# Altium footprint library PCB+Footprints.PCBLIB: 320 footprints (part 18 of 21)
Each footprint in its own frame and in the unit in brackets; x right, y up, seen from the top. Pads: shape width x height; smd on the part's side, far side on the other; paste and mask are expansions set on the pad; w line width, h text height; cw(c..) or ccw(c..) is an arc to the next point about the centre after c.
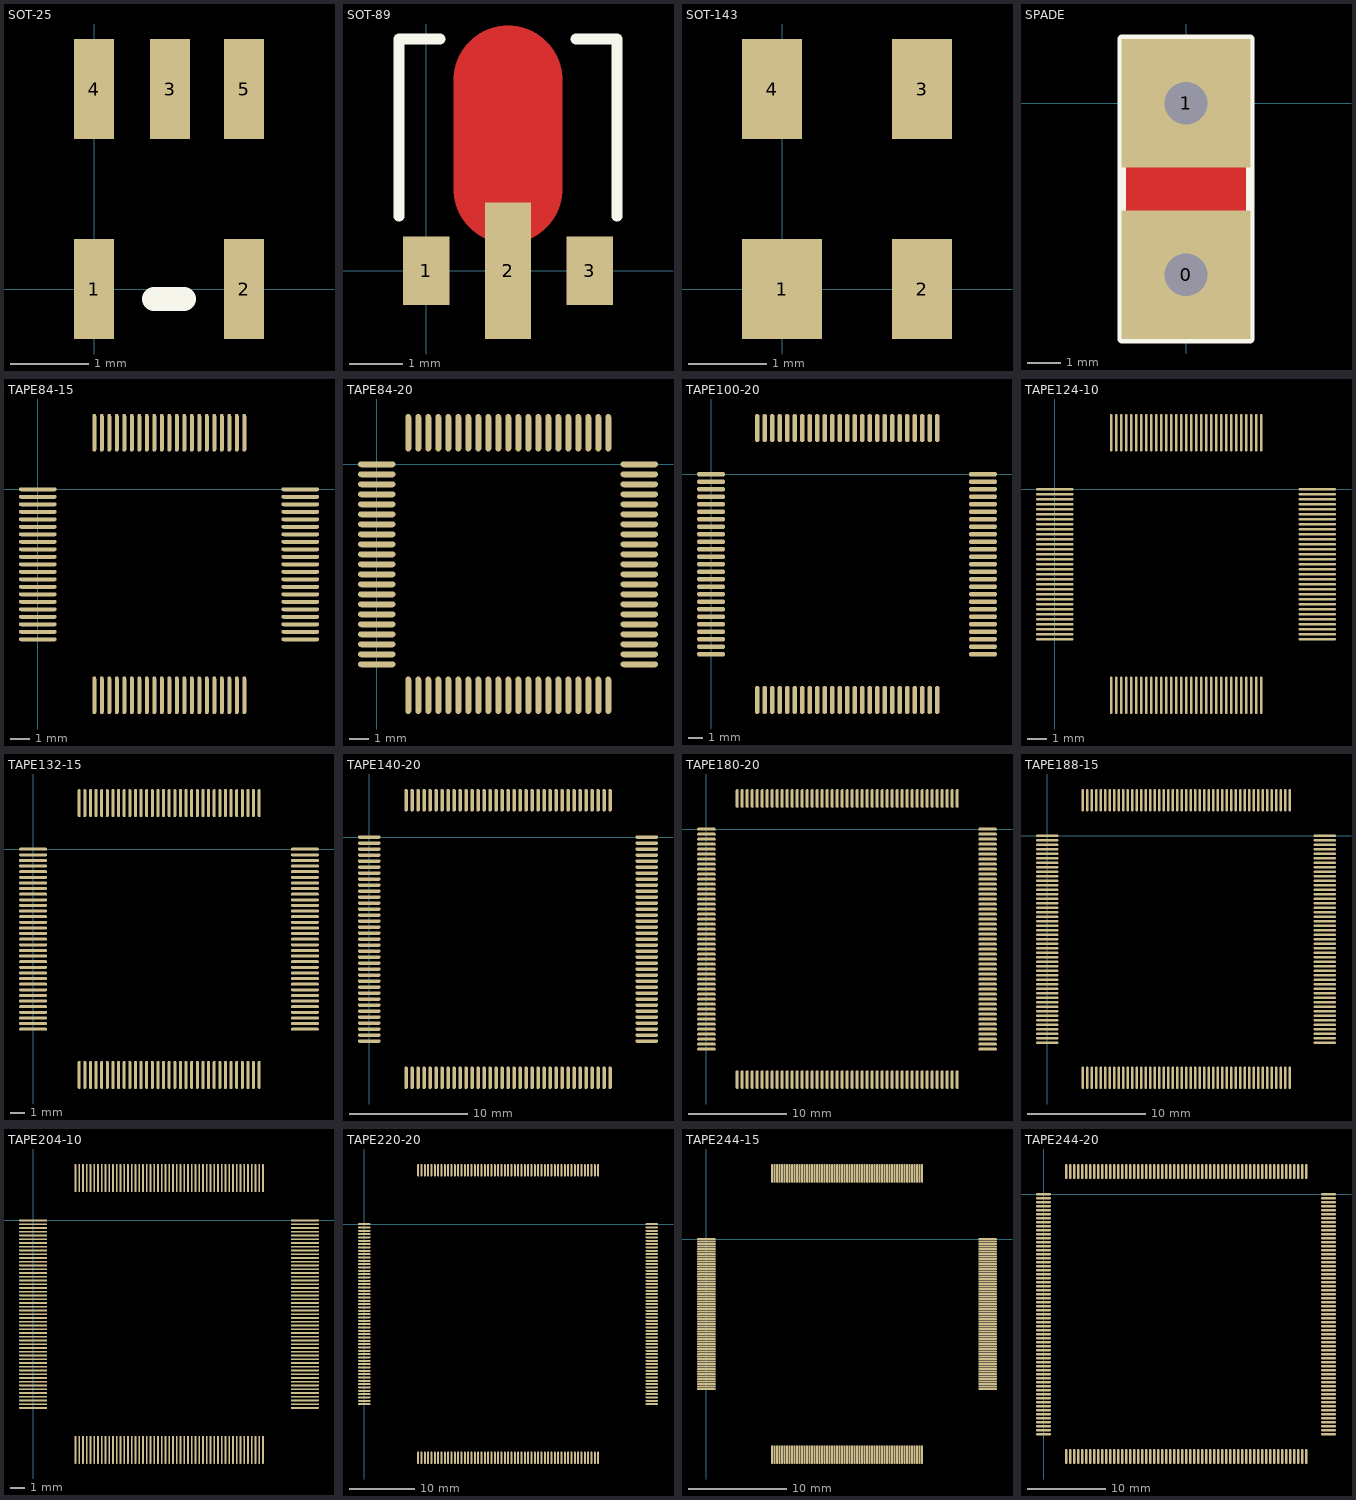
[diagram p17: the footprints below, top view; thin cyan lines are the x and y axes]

## SOT-25 [mil]
pads (5):
  rect 20x50 smd: 1(0,0) 2(75,0) 3(38,100) 4(0,100) 5(75,100)
TopOverlay:
  lines w12: 30,-5 45,-5

## SOT-89 [mil]
pads (3):
  rect 34x50 smd: 1(0,0) 3(120,0)
  rect 34x100 smd: 2(60,0)
TopLayer:
  lines w80: 60,60 60,140
TopOverlay:
  lines w8: -20,40 -20,170 10,170 ; 110,170 140,170 140,40

## SOT-143 [mil]
pads (4):
  rect 40x50 smd: 1(0,0)
  rect 30x50 smd: 2(70,0) 3(70,100) 4(-5,100)

## SPADE [mil]
pads (2):
  rect 150x150 hole 50: 0(0,-200) 1(0,0)
TopLayer:
  rectangle: -75,-150 75,-50
BottomLayer:
  rectangle: -75,-150 75,-50
TopOverlay:
  lines w10: -75,-275 75,-275 75,75 -75,75 -75,-275

## TAPE84-15 [mil]
pads (84):
  oval 75x8 smd: 1(0,0) 2(0,-15) 3(0,-30) 4(0,-45) 5(0,-60) 6(0,-75) 7(0,-90) 8(0,-105) 9(0,-120) 10(0,-135) 11(0,-150) 12(0,-165) 13(0,-180) 14(0,-195) 15(0,-210) 16(0,-225) 17(0,-240) 18(0,-255) 19(0,-270) 20(0,-285) 21(0,-300) 43(525,-300) 44(525,-285) 45(525,-270) 46(525,-255) 47(525,-240) 48(525,-225) 49(525,-210) 50(525,-195) 51(525,-180) 52(525,-165) 53(525,-150) 54(525,-135) 55(525,-120) 56(525,-105) 57(525,-90) 58(525,-75) 59(525,-60) 60(525,-45) 61(525,-30) 62(525,-15) 63(525,0)
  oval 8x75 smd: 22(113,-412) 23(128,-412) 24(143,-412) 25(158,-412) 26(173,-412) 27(188,-412) 28(203,-412) 29(218,-412) 30(233,-412) 31(248,-412) 32(263,-412) 33(278,-412) 34(293,-412) 35(308,-412) 36(323,-412) 37(338,-412) 38(353,-412) 39(368,-412) 40(383,-412) 41(398,-412) 42(413,-412) 64(413,113) 65(398,113) 66(383,113) 67(368,113) 68(353,113) 69(338,113) 70(323,113) 71(308,113) 72(293,113) 73(278,113) 74(263,113) 75(248,113) 76(233,113) 77(218,113) 78(203,113) 79(188,113) 80(173,113) 81(158,113) 82(143,113) 83(128,113) 84(113,113)

## TAPE84-20 [mil]
pads (84):
  oval 75x12 smd: 1(0,0) 2(0,-20) 3(0,-40) 4(0,-60) 5(0,-80) 6(0,-100) 7(0,-120) 8(0,-140) 9(0,-160) 10(0,-180) 11(0,-200) 12(0,-220) 13(0,-240) 14(0,-260) 15(0,-280) 16(0,-300) 17(0,-320) 18(0,-340) 19(0,-360) 20(0,-380) 21(0,-400) 43(525,-400) 44(525,-380) 45(525,-360) 46(525,-340) 47(525,-320) 48(525,-300) 49(525,-280) 50(525,-260) 51(525,-240) 52(525,-220) 53(525,-200) 54(525,-180) 55(525,-160) 56(525,-140) 57(525,-120) 58(525,-100) 59(525,-80) 60(525,-60) 61(525,-40) 62(525,-20) 63(525,0)
  oval 12x75 smd: 22(63,-462) 23(83,-462) 24(103,-462) 25(123,-462) 26(143,-462) 27(163,-462) 28(183,-462) 29(203,-462) 30(223,-462) 31(243,-462) 32(263,-462) 33(283,-462) 34(303,-462) 35(323,-462) 36(343,-462) 37(363,-462) 38(383,-462) 39(403,-462) 40(423,-462) 41(443,-462) 42(463,-462) 64(463,63) 65(443,63) 66(423,63) 67(403,63) 68(383,63) 69(363,63) 70(343,63) 71(323,63) 72(303,63) 73(283,63) 74(263,63) 75(243,63) 76(223,63) 77(203,63) 78(183,63) 79(163,63) 80(143,63) 81(123,63) 82(103,63) 83(83,63) 84(63,63)

## TAPE100-20 [mil]
pads (100):
  oval 75x12 smd: 1(0,0) 2(0,-20) 3(0,-40) 4(0,-60) 5(0,-80) 6(0,-100) 7(0,-120) 8(0,-140) 9(0,-160) 10(0,-180) 11(0,-200) 12(0,-220) 13(0,-240) 14(0,-260) 15(0,-280) 16(0,-300) 17(0,-320) 18(0,-340) 19(0,-360) 20(0,-380) 21(0,-400) 22(0,-420) 23(0,-440) 24(0,-460) 25(0,-480) 51(725,-480) 52(725,-460) 53(725,-440) 54(725,-420) 55(725,-400) 56(725,-380) 57(725,-360) 58(725,-340) 59(725,-320) 60(725,-300) 61(725,-280) 62(725,-260) 63(725,-240) 64(725,-220) 65(725,-200) 66(725,-180) 67(725,-160) 68(725,-140) 69(725,-120) 70(725,-100) 71(725,-80) 72(725,-60) 73(725,-40) 74(725,-20) 75(725,0)
  oval 12x75 smd: 26(123,-602) 27(143,-602) 28(163,-602) 29(183,-602) 30(203,-602) 31(223,-602) 32(243,-602) 33(263,-602) 34(283,-602) 35(303,-602) 36(323,-602) 37(343,-602) 38(363,-602) 39(383,-602) 40(403,-602) 41(423,-602) 42(443,-602) 43(463,-602) 44(483,-602) 45(503,-602) 46(523,-602) 47(543,-602) 48(563,-602) 49(583,-602) 50(603,-602) 76(603,123) 77(583,123) 78(563,123) 79(543,123) 80(523,123) 81(503,123) 82(483,123) 83(463,123) 84(443,123) 85(423,123) 86(403,123) 87(383,123) 88(363,123) 89(343,123) 90(323,123) 91(303,123) 92(283,123) 93(263,123) 94(243,123) 95(223,123) 96(203,123) 97(183,123) 98(163,123) 99(143,123) 100(123,123)

## TAPE124-10 [mil]
pads (124):
  oval 75x5 smd: 1(0,0) 2(0,-10) 3(0,-20) 4(0,-30) 5(0,-40) 6(0,-50) 7(0,-60) 8(0,-70) 9(0,-80) 10(0,-90) 11(0,-100) 12(0,-110) 13(0,-120) 14(0,-130) 15(0,-140) 16(0,-150) 17(0,-160) 18(0,-170) 19(0,-180) 20(0,-190) 21(0,-200) 22(0,-210) 23(0,-220) 24(0,-230) 25(0,-240) 26(0,-250) 27(0,-260) 28(0,-270) 29(0,-280) 30(0,-290) 31(0,-300) 63(525,-300) 64(525,-290) 65(525,-280) 66(525,-270) 67(525,-260) 68(525,-250) 69(525,-240) 70(525,-230) 71(525,-220) 72(525,-210) 73(525,-200) 74(525,-190) 75(525,-180) 76(525,-170) 77(525,-160) 78(525,-150) 79(525,-140) 80(525,-130) 81(525,-120) 82(525,-110) 83(525,-100) 84(525,-90) 85(525,-80) 86(525,-70) 87(525,-60) 88(525,-50) 89(525,-40) 90(525,-30) 91(525,-20) 92(525,-10) 93(525,0)
  oval 5x75 smd: 32(113,-412) 33(123,-412) 34(133,-412) 35(143,-412) 36(153,-412) 37(163,-412) 38(173,-412) 39(183,-412) 40(193,-412) 41(203,-412) 42(213,-412) 43(223,-412) 44(233,-412) 45(243,-412) 46(253,-412) 47(263,-412) 48(273,-412) 49(283,-412) 50(293,-412) 51(303,-412) 52(313,-412) 53(323,-412) 54(333,-412) 55(343,-412) 56(353,-412) 57(363,-412) 58(373,-412) 59(383,-412) 60(393,-412) 61(403,-412) 62(413,-412) 94(413,113) 95(403,113) 96(393,113) 97(383,113) 98(373,113) 99(363,113) 100(353,113) 101(343,113) 102(333,113) 103(323,113) 104(313,113) 105(303,113) 106(293,113) 107(283,113) 108(273,113) 109(263,113) 110(253,113) 111(243,113) 112(233,113) 113(223,113) 114(213,113) 115(203,113) 116(193,113) 117(183,113) 118(173,113) 119(163,113) 120(153,113) 121(143,113) 122(133,113) 123(123,113) 124(113,113)

## TAPE132-15 [mil]
pads (132):
  oval 75x8 smd: 1(0,0) 2(0,-15) 3(0,-30) 4(0,-45) 5(0,-60) 6(0,-75) 7(0,-90) 8(0,-105) 9(0,-120) 10(0,-135) 11(0,-150) 12(0,-165) 13(0,-180) 14(0,-195) 15(0,-210) 16(0,-225) 17(0,-240) 18(0,-255) 19(0,-270) 20(0,-285) 21(0,-300) 22(0,-315) 23(0,-330) 24(0,-345) 25(0,-360) 26(0,-375) 27(0,-390) 28(0,-405) 29(0,-420) 30(0,-435) 31(0,-450) 32(0,-465) 33(0,-480) 67(725,-480) 68(725,-465) 69(725,-450) 70(725,-435) 71(725,-420) 72(725,-405) 73(725,-390) 74(725,-375) 75(725,-360) 76(725,-345) 77(725,-330) 78(725,-315) 79(725,-300) 80(725,-285) 81(725,-270) 82(725,-255) 83(725,-240) 84(725,-225) 85(725,-210) 86(725,-195) 87(725,-180) 88(725,-165) 89(725,-150) 90(725,-135) 91(725,-120) 92(725,-105) 93(725,-90) 94(725,-75) 95(725,-60) 96(725,-45) 97(725,-30) 98(725,-15) 99(725,0)
  oval 8x75 smd: 34(123,-602) 35(138,-602) 36(153,-602) 37(168,-602) 38(183,-602) 39(198,-602) 40(213,-602) 41(228,-602) 42(243,-602) 43(258,-602) 44(273,-602) 45(288,-602) 46(303,-602) 47(318,-602) 48(333,-602) 49(348,-602) 50(363,-602) 51(378,-602) 52(393,-602) 53(408,-602) 54(423,-602) 55(438,-602) 56(453,-602) 57(468,-602) 58(483,-602) 59(498,-602) 60(513,-602) 61(528,-602) 62(543,-602) 63(558,-602) 64(573,-602) 65(588,-602) 66(603,-602) 100(603,123) 101(588,123) 102(573,123) 103(558,123) 104(543,123) 105(528,123) 106(513,123) 107(498,123) 108(483,123) 109(468,123) 110(453,123) 111(438,123) 112(423,123) 113(408,123) 114(393,123) 115(378,123) 116(363,123) 117(348,123) 118(333,123) 119(318,123) 120(303,123) 121(288,123) 122(273,123) 123(258,123) 124(243,123) 125(228,123) 126(213,123) 127(198,123) 128(183,123) 129(168,123) 130(153,123) 131(138,123) 132(123,123)

## TAPE140-20 [mil]
pads (140):
  oval 75x12 smd: 1(0,0) 2(0,-20) 3(0,-40) 4(0,-60) 5(0,-80) 6(0,-100) 7(0,-120) 8(0,-140) 9(0,-160) 10(0,-180) 11(0,-200) 12(0,-220) 13(0,-240) 14(0,-260) 15(0,-280) 16(0,-300) 17(0,-320) 18(0,-340) 19(0,-360) 20(0,-380) 21(0,-400) 22(0,-420) 23(0,-440) 24(0,-460) 25(0,-480) 26(0,-500) 27(0,-520) 28(0,-540) 29(0,-560) 30(0,-580) 31(0,-600) 32(0,-620) 33(0,-640) 34(0,-660) 35(0,-680) 71(925,-680) 72(925,-660) 73(925,-640) 74(925,-620) 75(925,-600) 76(925,-580) 77(925,-560) 78(925,-540) 79(925,-520) 80(925,-500) 81(925,-480) 82(925,-460) 83(925,-440) 84(925,-420) 85(925,-400) 86(925,-380) 87(925,-360) 88(925,-340) 89(925,-320) 90(925,-300) 91(925,-280) 92(925,-260) 93(925,-240) 94(925,-220) 95(925,-200) 96(925,-180) 97(925,-160) 98(925,-140) 99(925,-120) 100(925,-100) 101(925,-80) 102(925,-60) 103(925,-40) 104(925,-20) 105(925,0)
  oval 12x75 smd: 36(123,-802) 37(143,-802) 38(163,-802) 39(183,-802) 40(203,-802) 41(223,-802) 42(243,-802) 43(263,-802) 44(283,-802) 45(303,-802) 46(323,-802) 47(343,-802) 48(363,-802) 49(383,-802) 50(403,-802) 51(423,-802) 52(443,-802) 53(463,-802) 54(483,-802) 55(503,-802) 56(523,-802) 57(543,-802) 58(563,-802) 59(583,-802) 60(603,-802) 61(623,-802) 62(643,-802) 63(663,-802) 64(683,-802) 65(703,-802) 66(723,-802) 67(743,-802) 68(763,-802) 69(783,-802) 70(803,-802) 106(803,123) 107(783,123) 108(763,123) 109(743,123) 110(723,123) 111(703,123) 112(683,123) 113(663,123) 114(643,123) 115(623,123) 116(603,123) 117(583,123) 118(563,123) 119(543,123) 120(523,123) 121(503,123) 122(483,123) 123(463,123) 124(443,123) 125(423,123) 126(403,123) 127(383,123) 128(363,123) 129(343,123) 130(323,123) 131(303,123) 132(283,123) 133(263,123) 134(243,123) 135(223,123) 136(203,123) 137(183,123) 138(163,123) 139(143,123) 140(123,123)

## TAPE180-20 [mil]
pads (180):
  oval 75x12 smd: 1(0,0) 2(0,-20) 3(0,-40) 4(0,-60) 5(0,-80) 6(0,-100) 7(0,-120) 8(0,-140) 9(0,-160) 10(0,-180) 11(0,-200) 12(0,-220) 13(0,-240) 14(0,-260) 15(0,-280) 16(0,-300) 17(0,-320) 18(0,-340) 19(0,-360) 20(0,-380) 21(0,-400) 22(0,-420) 23(0,-440) 24(0,-460) 25(0,-480) 26(0,-500) 27(0,-520) 28(0,-540) 29(0,-560) 30(0,-580) 31(0,-600) 32(0,-620) 33(0,-640) 34(0,-660) 35(0,-680) 36(0,-700) 37(0,-720) 38(0,-740) 39(0,-760) 40(0,-780) 41(0,-800) 42(0,-820) 43(0,-840) 44(0,-860) 45(0,-880) 91(1125,-880) 92(1125,-860) 93(1125,-840) 94(1125,-820) 95(1125,-800) 96(1125,-780) 97(1125,-760) 98(1125,-740) 99(1125,-720) 100(1125,-700) 101(1125,-680) 102(1125,-660) 103(1125,-640) 104(1125,-620) 105(1125,-600) 106(1125,-580) 107(1125,-560) 108(1125,-540) 109(1125,-520) 110(1125,-500) 111(1125,-480) 112(1125,-460) 113(1125,-440) 114(1125,-420) 115(1125,-400) 116(1125,-380) 117(1125,-360) 118(1125,-340) 119(1125,-320) 120(1125,-300) 121(1125,-280) 122(1125,-260) 123(1125,-240) 124(1125,-220) 125(1125,-200) 126(1125,-180) 127(1125,-160) 128(1125,-140) 129(1125,-120) 130(1125,-100) 131(1125,-80) 132(1125,-60) 133(1125,-40) 134(1125,-20) 135(1125,0)
  oval 12x75 smd: 46(123,-1002) 47(143,-1002) 48(163,-1002) 49(183,-1002) 50(203,-1002) 51(223,-1002) 52(243,-1002) 53(263,-1002) 54(283,-1002) 55(303,-1002) 56(323,-1002) 57(343,-1002) 58(363,-1002) 59(383,-1002) 60(403,-1002) 61(423,-1002) 62(443,-1002) 63(463,-1002) 64(483,-1002) 65(503,-1002) 66(523,-1002) 67(543,-1002) 68(563,-1002) 69(583,-1002) 70(603,-1002) 71(623,-1002) 72(643,-1002) 73(663,-1002) 74(683,-1002) 75(703,-1002) 76(723,-1002) 77(743,-1002) 78(763,-1002) 79(783,-1002) 80(803,-1002) 81(823,-1002) 82(843,-1002) 83(863,-1002) 84(883,-1002) 85(903,-1002) 86(923,-1002) 87(943,-1002) 88(963,-1002) 89(983,-1002) 90(1003,-1002) 136(1003,123) 137(983,123) 138(963,123) 139(943,123) 140(923,123) 141(903,123) 142(883,123) 143(863,123) 144(843,123) 145(823,123) 146(803,123) 147(783,123) 148(763,123) 149(743,123) 150(723,123) 151(703,123) 152(683,123) 153(663,123) 154(643,123) 155(623,123) 156(603,123) 157(583,123) 158(563,123) 159(543,123) 160(523,123) 161(503,123) 162(483,123) 163(463,123) 164(443,123) 165(423,123) 166(403,123) 167(383,123) 168(363,123) 169(343,123) 170(323,123) 171(303,123) 172(283,123) 173(263,123) 174(243,123) 175(223,123) 176(203,123) 177(183,123) 178(163,123) 179(143,123) 180(123,123)

## TAPE188-15 [mil]
pads (188):
  oval 75x8 smd: 1(0,0) 2(0,-15) 3(0,-30) 4(0,-45) 5(0,-60) 6(0,-75) 7(0,-90) 8(0,-105) 9(0,-120) 10(0,-135) 11(0,-150) 12(0,-165) 13(0,-180) 14(0,-195) 15(0,-210) 16(0,-225) 17(0,-240) 18(0,-255) 19(0,-270) 20(0,-285) 21(0,-300) 22(0,-315) 23(0,-330) 24(0,-345) 25(0,-360) 26(0,-375) 27(0,-390) 28(0,-405) 29(0,-420) 30(0,-435) 31(0,-450) 32(0,-465) 33(0,-480) 34(0,-495) 35(0,-510) 36(0,-525) 37(0,-540) 38(0,-555) 39(0,-570) 40(0,-585) 41(0,-600) 42(0,-615) 43(0,-630) 44(0,-645) 45(0,-660) 46(0,-675) 47(0,-690) 95(925,-690) 96(925,-675) 97(925,-660) 98(925,-645) 99(925,-630) 100(925,-615) 101(925,-600) 102(925,-585) 103(925,-570) 104(925,-555) 105(925,-540) 106(925,-525) 107(925,-510) 108(925,-495) 109(925,-480) 110(925,-465) 111(925,-450) 112(925,-435) 113(925,-420) 114(925,-405) 115(925,-390) 116(925,-375) 117(925,-360) 118(925,-345) 119(925,-330) 120(925,-315) 121(925,-300) 122(925,-285) 123(925,-270) 124(925,-255) 125(925,-240) 126(925,-225) 127(925,-210) 128(925,-195) 129(925,-180) 130(925,-165) 131(925,-150) 132(925,-135) 133(925,-120) 134(925,-105) 135(925,-90) 136(925,-75) 137(925,-60) 138(925,-45) 139(925,-30) 140(925,-15) 141(925,0)
  oval 8x75 smd: 48(118,-807) 49(133,-807) 50(148,-807) 51(163,-807) 52(178,-807) 53(193,-807) 54(208,-807) 55(223,-807) 56(238,-807) 57(253,-807) 58(268,-807) 59(283,-807) 60(298,-807) 61(313,-807) 62(328,-807) 63(343,-807) 64(358,-807) 65(373,-807) 66(388,-807) 67(403,-807) 68(418,-807) 69(433,-807) 70(448,-807) 71(463,-807) 72(478,-807) 73(493,-807) 74(508,-807) 75(523,-807) 76(538,-807) 77(553,-807) 78(568,-807) 79(583,-807) 80(598,-807) 81(613,-807) 82(628,-807) 83(643,-807) 84(658,-807) 85(673,-807) 86(688,-807) 87(703,-807) 88(718,-807) 89(733,-807) 90(748,-807) 91(763,-807) 92(778,-807) 93(793,-807) 94(808,-807) 142(808,118) 143(793,118) 144(778,118) 145(763,118) 146(748,118) 147(733,118) 148(718,118) 149(703,118) 150(688,118) 151(673,118) 152(658,118) 153(643,118) 154(628,118) 155(613,118) 156(598,118) 157(583,118) 158(568,118) 159(553,118) 160(538,118) 161(523,118) 162(508,118) 163(493,118) 164(478,118) 165(463,118) 166(448,118) 167(433,118) 168(418,118) 169(403,118) 170(388,118) 171(373,118) 172(358,118) 173(343,118) 174(328,118) 175(313,118) 176(298,118) 177(283,118) 178(268,118) 179(253,118) 180(238,118) 181(223,118) 182(208,118) 183(193,118) 184(178,118) 185(163,118) 186(148,118) 187(133,118) 188(118,118)

## TAPE204-10 [mil]
pads (204):
  oval 75x5 smd: 1(0,0) 2(0,-10) 3(0,-20) 4(0,-30) 5(0,-40) 6(0,-50) 7(0,-60) 8(0,-70) 9(0,-80) 10(0,-90) 11(0,-100) 12(0,-110) 13(0,-120) 14(0,-130) 15(0,-140) 16(0,-150) 17(0,-160) 18(0,-170) 19(0,-180) 20(0,-190) 21(0,-200) 22(0,-210) 23(0,-220) 24(0,-230) 25(0,-240) 26(0,-250) 27(0,-260) 28(0,-270) 29(0,-280) 30(0,-290) 31(0,-300) 32(0,-310) 33(0,-320) 34(0,-330) 35(0,-340) 36(0,-350) 37(0,-360) 38(0,-370) 39(0,-380) 40(0,-390) 41(0,-400) 42(0,-410) 43(0,-420) 44(0,-430) 45(0,-440) 46(0,-450) 47(0,-460) 48(0,-470) 49(0,-480) 50(0,-490) 51(0,-500) 103(725,-500) 104(725,-490) 105(725,-480) 106(725,-470) 107(725,-460) 108(725,-450) 109(725,-440) 110(725,-430) 111(725,-420) 112(725,-410) 113(725,-400) 114(725,-390) 115(725,-380) 116(725,-370) 117(725,-360) 118(725,-350) 119(725,-340) 120(725,-330) 121(725,-320) 122(725,-310) 123(725,-300) 124(725,-290) 125(725,-280) 126(725,-270) 127(725,-260) 128(725,-250) 129(725,-240) 130(725,-230) 131(725,-220) 132(725,-210) 133(725,-200) 134(725,-190) 135(725,-180) 136(725,-170) 137(725,-160) 138(725,-150) 139(725,-140) 140(725,-130) 141(725,-120) 142(725,-110) 143(725,-100) 144(725,-90) 145(725,-80) 146(725,-70) 147(725,-60) 148(725,-50) 149(725,-40) 150(725,-30) 151(725,-20) 152(725,-10) 153(725,0)
  oval 5x75 smd: 52(113,-612) 53(123,-612) 54(133,-612) 55(143,-612) 56(153,-612) 57(163,-612) 58(173,-612) 59(183,-612) 60(193,-612) 61(203,-612) 62(213,-612) 63(223,-612) 64(233,-612) 65(243,-612) 66(253,-612) 67(263,-612) 68(273,-612) 69(283,-612) 70(293,-612) 71(303,-612) 72(313,-612) 73(323,-612) 74(333,-612) 75(343,-612) 76(353,-612) 77(363,-612) 78(373,-612) 79(383,-612) 80(393,-612) 81(403,-612) 82(413,-612) 83(423,-612) 84(433,-612) 85(443,-612) 86(453,-612) 87(463,-612) 88(473,-612) 89(483,-612) 90(493,-612) 91(503,-612) 92(513,-612) 93(523,-612) 94(533,-612) 95(543,-612) 96(553,-612) 97(563,-612) 98(573,-612) 99(583,-612) 100(593,-612) 101(603,-612) 102(613,-612) 154(613,113) 155(603,113) 156(593,113) 157(583,113) 158(573,113) 159(563,113) 160(553,113) 161(543,113) 162(533,113) 163(523,113) 164(513,113) 165(503,113) 166(493,113) 167(483,113) 168(473,113) 169(463,113) 170(453,113) 171(443,113) 172(433,113) 173(423,113) 174(413,113) 175(403,113) 176(393,113) 177(383,113) 178(373,113) 179(363,113) 180(353,113) 181(343,113) 182(333,113) 183(323,113) 184(313,113) 185(303,113) 186(293,113) 187(283,113) 188(273,113) 189(263,113) 190(253,113) 191(243,113) 192(233,113) 193(223,113) 194(213,113) 195(203,113) 196(193,113) 197(183,113) 198(173,113) 199(163,113) 200(153,113) 201(143,113) 202(133,113) 203(123,113) 204(113,113)

## TAPE220-20 [mil]
pads (220):
  oval 75x12 smd: 1(0,0) 2(0,-20) 3(0,-40) 4(0,-60) 5(0,-80) 6(0,-100) 7(0,-120) 8(0,-140) 9(0,-160) 10(0,-180) 11(0,-200) 12(0,-220) 13(0,-240) 14(0,-260) 15(0,-280) 16(0,-300) 17(0,-320) 18(0,-340) 19(0,-360) 20(0,-380) 21(0,-400) 22(0,-420) 23(0,-440) 24(0,-460) 25(0,-480) 26(0,-500) 27(0,-520) 28(0,-540) 29(0,-560) 30(0,-580) 31(0,-600) 32(0,-620) 33(0,-640) 34(0,-660) 35(0,-680) 36(0,-700) 37(0,-720) 38(0,-740) 39(0,-760) 40(0,-780) 41(0,-800) 42(0,-820) 43(0,-840) 44(0,-860) 45(0,-880) 46(0,-900) 47(0,-920) 48(0,-940) 49(0,-960) 50(0,-980) 51(0,-1000) 52(0,-1020) 53(0,-1040) 54(0,-1060) 55(0,-1080) 111(1725,-1080) 112(1725,-1060) 113(1725,-1040) 114(1725,-1020) 115(1725,-1000) 116(1725,-980) 117(1725,-960) 118(1725,-940) 119(1725,-920) 120(1725,-900) 121(1725,-880) 122(1725,-860) 123(1725,-840) 124(1725,-820) 125(1725,-800) 126(1725,-780) 127(1725,-760) 128(1725,-740) 129(1725,-720) 130(1725,-700) 131(1725,-680) 132(1725,-660) 133(1725,-640) 134(1725,-620) 135(1725,-600) 136(1725,-580) 137(1725,-560) 138(1725,-540) 139(1725,-520) 140(1725,-500) 141(1725,-480) 142(1725,-460) 143(1725,-440) 144(1725,-420) 145(1725,-400) 146(1725,-380) 147(1725,-360) 148(1725,-340) 149(1725,-320) 150(1725,-300) 151(1725,-280) 152(1725,-260) 153(1725,-240) 154(1725,-220) 155(1725,-200) 156(1725,-180) 157(1725,-160) 158(1725,-140) 159(1725,-120) 160(1725,-100) 161(1725,-80) 162(1725,-60) 163(1725,-40) 164(1725,-20) 165(1725,0)
  oval 12x75 smd: 56(323,-1402) 57(343,-1402) 58(363,-1402) 59(383,-1402) 60(403,-1402) 61(423,-1402) 62(443,-1402) 63(463,-1402) 64(483,-1402) 65(503,-1402) 66(523,-1402) 67(543,-1402) 68(563,-1402) 69(583,-1402) 70(603,-1402) 71(623,-1402) 72(643,-1402) 73(663,-1402) 74(683,-1402) 75(703,-1402) 76(723,-1402) 77(743,-1402) 78(763,-1402) 79(783,-1402) 80(803,-1402) 81(823,-1402) 82(843,-1402) 83(863,-1402) 84(883,-1402) 85(903,-1402) 86(923,-1402) 87(943,-1402) 88(963,-1402) 89(983,-1402) 90(1003,-1402) 91(1023,-1402) 92(1043,-1402) 93(1063,-1402) 94(1083,-1402) 95(1103,-1402) 96(1123,-1402) 97(1143,-1402) 98(1163,-1402) 99(1183,-1402) 100(1203,-1402) 101(1223,-1402) 102(1243,-1402) 103(1263,-1402) 104(1283,-1402) 105(1303,-1402) 106(1323,-1402) 107(1343,-1402) 108(1363,-1402) 109(1383,-1402) 110(1403,-1402) 166(1403,323) 167(1383,323) 168(1363,323) 169(1343,323) 170(1323,323) 171(1303,323) 172(1283,323) 173(1263,323) 174(1243,323) 175(1223,323) 176(1203,323) 177(1183,323) 178(1163,323) 179(1143,323) 180(1123,323) 181(1103,323) 182(1083,323) 183(1063,323) 184(1043,323) 185(1023,323) 186(1003,323) 187(983,323) 188(963,323) 189(943,323) 190(923,323) 191(903,323) 192(883,323) 193(863,323) 194(843,323) 195(823,323) 196(803,323) 197(783,323) 198(763,323) 199(743,323) 200(723,323) 201(703,323) 202(683,323) 203(663,323) 204(643,323) 205(623,323) 206(603,323) 207(583,323) 208(563,323) 209(543,323) 210(523,323) 211(503,323) 212(483,323) 213(463,323) 214(443,323) 215(423,323) 216(403,323) 217(383,323) 218(363,323) 219(343,323) 220(323,323)

## TAPE244-15 [mil]
pads (244):
  oval 75x8 smd: 1(0,0) 2(0,-10) 3(0,-20) 4(0,-30) 5(0,-40) 6(0,-50) 7(0,-60) 8(0,-70) 9(0,-80) 10(0,-90) 11(0,-100) 12(0,-110) 13(0,-120) 14(0,-130) 15(0,-140) 16(0,-150) 17(0,-160) 18(0,-170) 19(0,-180) 20(0,-190) 21(0,-200) 22(0,-210) 23(0,-220) 24(0,-230) 25(0,-240) 26(0,-250) 27(0,-260) 28(0,-270) 29(0,-280) 30(0,-290) 31(0,-300) 32(0,-310) 33(0,-320) 34(0,-330) 35(0,-340) 36(0,-350) 37(0,-360) 38(0,-370) 39(0,-380) 40(0,-390) 41(0,-400) 42(0,-410) 43(0,-420) 44(0,-430) 45(0,-440) 46(0,-450) 47(0,-460) 48(0,-470) 49(0,-480) 50(0,-490) 51(0,-500) 52(0,-510) 53(0,-520) 54(0,-530) 55(0,-540) 56(0,-550) 57(0,-560) 58(0,-570) 59(0,-580) 60(0,-590) 61(0,-600) 123(1125,-600) 124(1125,-590) 125(1125,-580) 126(1125,-570) 127(1125,-560) 128(1125,-550) 129(1125,-540) 130(1125,-530) 131(1125,-520) 132(1125,-510) 133(1125,-500) 134(1125,-490) 135(1125,-480) 136(1125,-470) 137(1125,-460) 138(1125,-450) 139(1125,-440) 140(1125,-430) 141(1125,-420) 142(1125,-410) 143(1125,-400) 144(1125,-390) 145(1125,-380) 146(1125,-370) 147(1125,-360) 148(1125,-350) 149(1125,-340) 150(1125,-330) 151(1125,-320) 152(1125,-310) 153(1125,-300) 154(1125,-290) 155(1125,-280) 156(1125,-270) 157(1125,-260) 158(1125,-250) 159(1125,-240) 160(1125,-230) 161(1125,-220) 162(1125,-210) 163(1125,-200) 164(1125,-190) 165(1125,-180) 166(1125,-170) 167(1125,-160) 168(1125,-150) 169(1125,-140) 170(1125,-130) 171(1125,-120) 172(1125,-110) 173(1125,-100) 174(1125,-90) 175(1125,-80) 176(1125,-70) 177(1125,-60) 178(1125,-50) 179(1125,-40) 180(1125,-30) 181(1125,-20) 182(1125,-10) 183(1125,0)
  oval 8x75 smd: 62(263,-862) 63(273,-862) 64(283,-862) 65(293,-862) 66(303,-862) 67(313,-862) 68(323,-862) 69(333,-862) 70(343,-862) 71(353,-862) 72(363,-862) 73(373,-862) 74(383,-862) 75(393,-862) 76(403,-862) 77(413,-862) 78(423,-862) 79(433,-862) 80(443,-862) 81(453,-862) 82(463,-862) 83(473,-862) 84(483,-862) 85(493,-862) 86(503,-862) 87(513,-862) 88(523,-862) 89(533,-862) 90(543,-862) 91(553,-862) 92(563,-862) 93(573,-862) 94(583,-862) 95(593,-862) 96(603,-862) 97(613,-862) 98(623,-862) 99(633,-862) 100(643,-862) 101(653,-862) 102(663,-862) 103(673,-862) 104(683,-862) 105(693,-862) 106(703,-862) 107(713,-862) 108(723,-862) 109(733,-862) 110(743,-862) 111(753,-862) 112(763,-862) 113(773,-862) 114(783,-862) 115(793,-862) 116(803,-862) 117(813,-862) 118(823,-862) 119(833,-862) 120(843,-862) 121(853,-862) 122(863,-862) 184(863,263) 185(853,263) 186(843,263) 187(833,263) 188(823,263) 189(813,263) 190(803,263) 191(793,263) 192(783,263) 193(773,263) 194(763,263) 195(753,263) 196(743,263) 197(733,263) 198(723,263) 199(713,263) 200(703,263) 201(693,263) 202(683,263) 203(673,263) 204(663,263) 205(653,263) 206(643,263) 207(633,263) 208(623,263) 209(613,263) 210(603,263) 211(593,263) 212(583,263) 213(573,263) 214(563,263) 215(553,263) 216(543,263) 217(533,263) 218(523,263) 219(513,263) 220(503,263) 221(493,263) 222(483,263) 223(473,263) 224(463,263) 225(453,263) 226(443,263) 227(433,263) 228(423,263) 229(413,263) 230(403,263) 231(393,263) 232(383,263) 233(373,263) 234(363,263) 235(353,263) 236(343,263) 237(333,263) 238(323,263) 239(313,263) 240(303,263) 241(293,263) 242(283,263) 243(273,263) 244(263,263)

## TAPE244-20 [mil]
pads (244):
  oval 75x12 smd: 1(0,0) 2(0,-20) 3(0,-40) 4(0,-60) 5(0,-80) 6(0,-100) 7(0,-120) 8(0,-140) 9(0,-160) 10(0,-180) 11(0,-200) 12(0,-220) 13(0,-240) 14(0,-260) 15(0,-280) 16(0,-300) 17(0,-320) 18(0,-340) 19(0,-360) 20(0,-380) 21(0,-400) 22(0,-420) 23(0,-440) 24(0,-460) 25(0,-480) 26(0,-500) 27(0,-520) 28(0,-540) 29(0,-560) 30(0,-580) 31(0,-600) 32(0,-620) 33(0,-640) 34(0,-660) 35(0,-680) 36(0,-700) 37(0,-720) 38(0,-740) 39(0,-760) 40(0,-780) 41(0,-800) 42(0,-820) 43(0,-840) 44(0,-860) 45(0,-880) 46(0,-900) 47(0,-920) 48(0,-940) 49(0,-960) 50(0,-980) 51(0,-1000) 52(0,-1020) 53(0,-1040) 54(0,-1060) 55(0,-1080) 56(0,-1100) 57(0,-1120) 58(0,-1140) 59(0,-1160) 60(0,-1180) 61(0,-1200) 123(1425,-1200) 124(1425,-1180) 125(1425,-1160) 126(1425,-1140) 127(1425,-1120) 128(1425,-1100) 129(1425,-1080) 130(1425,-1060) 131(1425,-1040) 132(1425,-1020) 133(1425,-1000) 134(1425,-980) 135(1425,-960) 136(1425,-940) 137(1425,-920) 138(1425,-900) 139(1425,-880) 140(1425,-860) 141(1425,-840) 142(1425,-820) 143(1425,-800) 144(1425,-780) 145(1425,-760) 146(1425,-740) 147(1425,-720) 148(1425,-700) 149(1425,-680) 150(1425,-660) 151(1425,-640) 152(1425,-620) 153(1425,-600) 154(1425,-580) 155(1425,-560) 156(1425,-540) 157(1425,-520) 158(1425,-500) 159(1425,-480) 160(1425,-460) 161(1425,-440) 162(1425,-420) 163(1425,-400) 164(1425,-380) 165(1425,-360) 166(1425,-340) 167(1425,-320) 168(1425,-300) 169(1425,-280) 170(1425,-260) 171(1425,-240) 172(1425,-220) 173(1425,-200) 174(1425,-180) 175(1425,-160) 176(1425,-140) 177(1425,-120) 178(1425,-100) 179(1425,-80) 180(1425,-60) 181(1425,-40) 182(1425,-20) 183(1425,0)
  oval 12x75 smd: 62(113,-1312) 63(133,-1312) 64(153,-1312) 65(173,-1312) 66(193,-1312) 67(213,-1312) 68(233,-1312) 69(253,-1312) 70(273,-1312) 71(293,-1312) 72(313,-1312) 73(333,-1312) 74(353,-1312) 75(373,-1312) 76(393,-1312) 77(413,-1312) 78(433,-1312) 79(453,-1312) 80(473,-1312) 81(493,-1312) 82(513,-1312) 83(533,-1312) 84(553,-1312) 85(573,-1312) 86(593,-1312) 87(613,-1312) 88(633,-1312) 89(653,-1312) 90(673,-1312) 91(693,-1312) 92(713,-1312) 93(733,-1312) 94(753,-1312) 95(773,-1312) 96(793,-1312) 97(813,-1312) 98(833,-1312) 99(853,-1312) 100(873,-1312) 101(893,-1312) 102(913,-1312) 103(933,-1312) 104(953,-1312) 105(973,-1312) 106(993,-1312) 107(1013,-1312) 108(1033,-1312) 109(1053,-1312) 110(1073,-1312) 111(1093,-1312) 112(1113,-1312) 113(1133,-1312) 114(1153,-1312) 115(1173,-1312) 116(1193,-1312) 117(1213,-1312) 118(1233,-1312) 119(1253,-1312) 120(1273,-1312) 121(1293,-1312) 122(1313,-1312) 184(1313,113) 185(1293,113) 186(1273,113) 187(1253,113) 188(1233,113) 189(1213,113) 190(1193,113) 191(1173,113) 192(1153,113) 193(1133,113) 194(1113,113) 195(1093,113) 196(1073,113) 197(1053,113) 198(1033,113) 199(1013,113) 200(993,113) 201(973,113) 202(953,113) 203(933,113) 204(913,113) 205(893,113) 206(873,113) 207(853,113) 208(833,113) 209(813,113) 210(793,113) 211(773,113) 212(753,113) 213(733,113) 214(713,113) 215(693,113) 216(673,113) 217(653,113) 218(633,113) 219(613,113) 220(593,113) 221(573,113) 222(553,113) 223(533,113) 224(513,113) 225(493,113) 226(473,113) 227(453,113) 228(433,113) 229(413,113) 230(393,113) 231(373,113) 232(353,113) 233(333,113) 234(313,113) 235(293,113) 236(273,113) 237(253,113) 238(233,113) 239(213,113) 240(193,113) 241(173,113) 242(153,113) 243(133,113) 244(113,113)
